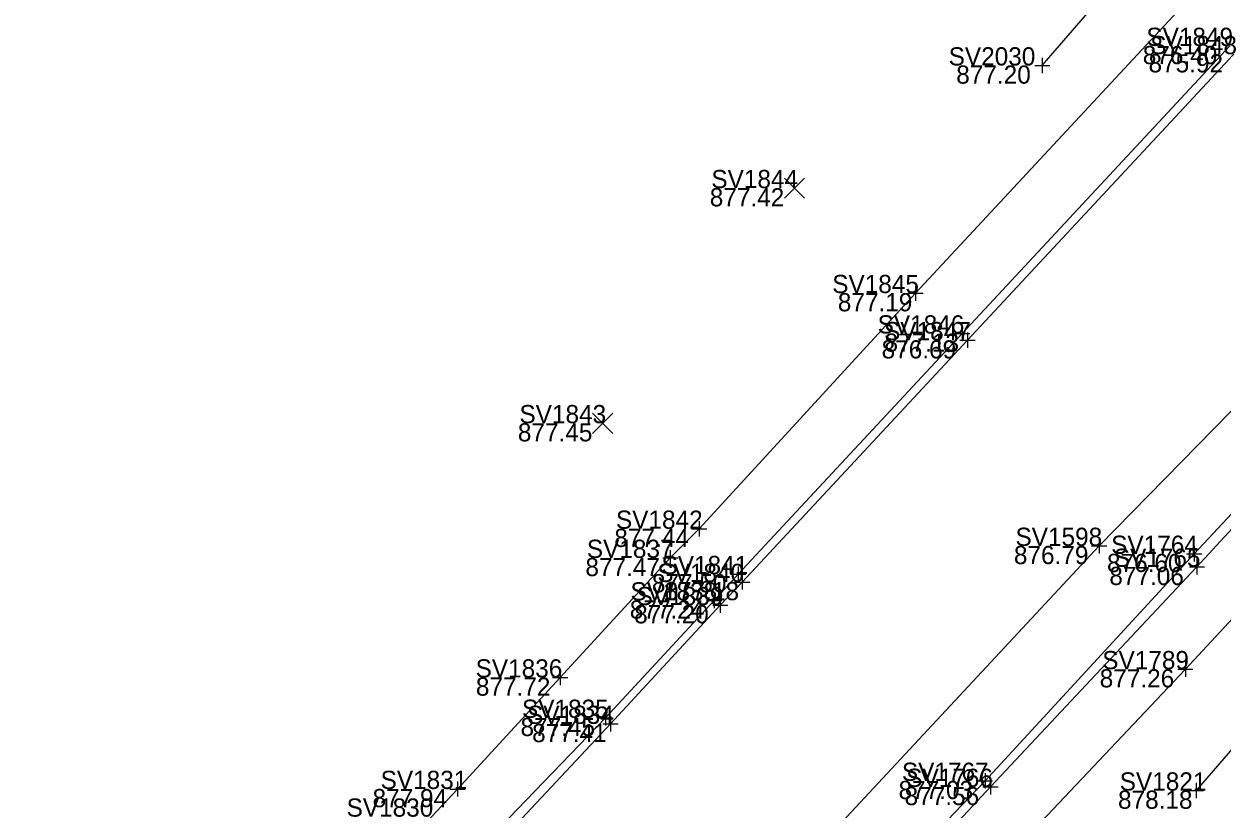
# Model space of a CAD drawing. Extents: x 1480001 to 1480402, y 379235 to 379603.
# Drawn here: x 1480035.5 to 1480114.4, y 379318.4 to 379370.1 of the extents above; entities that cross this region are included whole.
import ezdxf

# ---------------------------------------------------------------- set-up
doc = ezdxf.new("R2010")
doc.units = 0
for name, color, linetype in [('PV_X_Curb', 7, 'Continuous'), ('PV_X_Walk', 7, 'Continuous'), ('SV_X_Break_Lines', 7, 'Continuous'), ('SV_X_Random_Point', 7, 'Continuous'), ('SV_X_Shot_Marker', 7, 'Continuous'), ('SV_X_Text_Elevation', 7, 'Continuous'), ('SV_X_Text_Name', 7, 'Continuous'), ('UT_X_Water', 7, 'Continuous')]:
    doc.layers.add(name, color=color, linetype=linetype)

msp = doc.modelspace()

# ---------------------------------------------------------------- linework, layer by layer
at = {"layer": 'PV_X_Curb'}
for points in [[(1480155.238, 379379.795), (1480153.548, 379379.014), (1480146.824, 379371.927), (1480145.567, 379370.605), (1480143.964, 379368.78), (1480128.12, 379351.892), (1480112.56, 379335.214), (1480098.785, 379320.255), (1480094.793, 379316.092), (1480093.124, 379314.172), (1480085.166, 379305.624), (1480081.585, 379301.702), (1480079.854, 379299.882), (1480067.172, 379286.11), (1480056.531, 379274.485), (1480055.169, 379272.969)], [(1480155.431, 379379.884), (1480153.98, 379378.667), (1480147.216, 379371.505), (1480146.047, 379370.27), (1480144.119, 379368.047), (1480128.647, 379351.629), (1480112.741, 379334.357), (1480099.146, 379319.858), (1480095.569, 379316.008), (1480093.53, 379313.846), (1480085.356, 379305.01), (1480081.967, 379301.397), (1480080.218, 379299.413), (1480067.589, 379285.613), (1480056.688, 379273.774), (1480055.547, 379272.623)], [(1480038.409, 379286.458), (1480053.445, 379302.656), (1480065.083, 379315.224), (1480066.832, 379317.181), (1480073.782, 379324.407), (1480080.94, 379332.144), (1480082.529, 379333.877), (1480097.272, 379349.731), (1480114.906, 379368.678)], [(1480038.979, 379286.174), (1480053.858, 379302.215), (1480065.464, 379314.71), (1480067.296, 379316.727), (1480074.111, 379324.008), (1480081.345, 379331.835), (1480082.794, 379333.357), (1480097.622, 379349.287), (1480115.163, 379368.135)]]:
    msp.add_lwpolyline(points, dxfattribs=at)
at = {"layer": 'PV_X_Walk'}
for points in [[(1480035.484, 379289.224), (1480050.568, 379305.437), (1480062.335, 379317.896), (1480064.038, 379319.719), (1480070.805, 379327.066), (1480078.054, 379334.946), (1480079.953, 379336.866), (1480094.208, 379352.393), (1480112.048, 379371.575), (1480117.348, 379377.211), (1480119.911, 379379.906), (1480121.511, 379381.77), (1480134.604, 379395.58), (1480136.695, 379398.148), (1480138.778, 379401.149), (1480140.004, 379404.725), (1480140.577, 379408.06), (1480140.982, 379411.311), (1480140.871, 379414.584), (1480140.225, 379417.636), (1480139.184, 379419.586), (1480133.124, 379425.845), (1480132.903, 379425.968), (1480114.834, 379442.96)], [(1480059.793, 379271.54), (1480075.261, 379288.048), (1480088.444, 379302.419), (1480096.088, 379310.695), (1480098.33, 379313.163), (1480111.975, 379327.613), (1480128.977, 379345.933), (1480145.46, 379363.52), (1480153.413, 379372.021), (1480155.772, 379374.786), (1480158.213, 379377.107), (1480160.137, 379378.801), (1480161.631, 379379.994)]]:
    msp.add_lwpolyline(points, dxfattribs=at)
at = {"layer": 'SV_X_Break_Lines'}
for points in [[(1480102.555, 379367.391), (1480110.126, 379376.156), (1480117.553, 379385.207), (1480124.442, 379393.548)], [(1480184.481, 379363.392), (1480180.224, 379367.084), (1480176.21, 379371.695), (1480171.222, 379375.535), (1480168.077, 379375.239), (1480160.326, 379371.415), (1480150.91, 379361.854), (1480140.301, 379350.86), (1480130.798, 379340.93), (1480121.664, 379330.001), (1480112.679, 379319.616)]]:
    msp.add_lwpolyline(points, dxfattribs=at)
at = {"layer": 'SV_X_Random_Point'}
for p, q in [((1480085.569, 379358.641), (1480086.903, 379359.976)), ((1480085.569, 379359.976), (1480086.903, 379358.641)), ((1480072.94, 379343.152), (1480074.274, 379344.487)), ((1480072.94, 379344.487), (1480074.274, 379343.152))]:
    msp.add_line(p, q, dxfattribs=at)
at = {"layer": 'SV_X_Shot_Marker'}
for p, q in [((1480102.555, 379367.891), (1480102.555, 379366.891)), ((1480102.055, 379367.391), (1480103.055, 379367.391)), ((1480102.555, 379367.391), (1480102.555, 379367.391)), ((1480094.208, 379352.893), (1480094.208, 379351.893)), ((1480093.708, 379352.393), (1480094.708, 379352.393)), ((1480094.208, 379352.393), (1480094.208, 379352.393)), ((1480096.772, 379349.731), (1480097.772, 379349.731)), ((1480097.272, 379350.231), (1480097.272, 379349.231)), ((1480097.272, 379349.731), (1480097.272, 379349.731)), ((1480097.622, 379349.787), (1480097.622, 379348.787)), ((1480097.122, 379349.287), (1480098.122, 379349.287)), ((1480097.622, 379349.287), (1480097.622, 379349.287)), ((1480079.953, 379337.366), (1480079.953, 379336.366)), ((1480079.453, 379336.866), (1480080.453, 379336.866)), ((1480079.953, 379336.866), (1480079.953, 379336.866)), ((1480105.797, 379335.736), (1480106.797, 379335.736)), ((1480106.297, 379336.236), (1480106.297, 379335.236)), ((1480106.297, 379335.736), (1480106.297, 379335.736)), ((1480112.56, 379335.714), (1480112.56, 379334.714)), ((1480077.554, 379334.946), (1480078.554, 379334.946)), ((1480078.054, 379335.446), (1480078.054, 379334.446)), ((1480078.054, 379334.946), (1480078.054, 379334.946)), ((1480112.06, 379335.214), (1480113.06, 379335.214)), ((1480112.56, 379335.214), (1480112.56, 379335.214)), ((1480112.741, 379334.857), (1480112.741, 379333.857)), ((1480082.529, 379334.377), (1480082.529, 379333.377)), ((1480112.241, 379334.357), (1480113.241, 379334.357)), ((1480112.741, 379334.357), (1480112.741, 379334.357)), ((1480082.029, 379333.877), (1480083.029, 379333.877)), ((1480082.294, 379333.357), (1480083.294, 379333.357)), ((1480082.529, 379333.877), (1480082.529, 379333.877)), ((1480082.794, 379333.857), (1480082.794, 379332.857)), ((1480082.794, 379333.357), (1480082.794, 379333.357)), ((1480080.94, 379332.644), (1480080.94, 379331.644)), ((1480081.345, 379332.335), (1480081.345, 379331.335)), ((1480080.44, 379332.144), (1480081.44, 379332.144)), ((1480080.845, 379331.835), (1480081.845, 379331.835)), ((1480080.94, 379332.144), (1480080.94, 379332.144)), ((1480081.345, 379331.835), (1480081.345, 379331.835)), ((1480070.805, 379327.566), (1480070.805, 379326.566)), ((1480111.475, 379327.613), (1480112.475, 379327.613)), ((1480111.975, 379328.113), (1480111.975, 379327.113)), ((1480111.975, 379327.613), (1480111.975, 379327.613)), ((1480070.305, 379327.066), (1480071.305, 379327.066)), ((1480070.805, 379327.066), (1480070.805, 379327.066)), ((1480073.782, 379324.907), (1480073.782, 379323.907)), ((1480074.111, 379324.508), (1480074.111, 379323.508)), ((1480073.282, 379324.407), (1480074.282, 379324.407)), ((1480073.611, 379324.008), (1480074.611, 379324.008)), ((1480073.782, 379324.407), (1480073.782, 379324.407)), ((1480074.111, 379324.008), (1480074.111, 379324.008)), ((1480098.785, 379320.755), (1480098.785, 379319.755)), ((1480063.538, 379319.719), (1480064.538, 379319.719)), ((1480064.038, 379320.219), (1480064.038, 379319.219)), ((1480064.038, 379319.719), (1480064.038, 379319.719)), ((1480098.285, 379320.255), (1480099.285, 379320.255)), ((1480098.646, 379319.858), (1480099.646, 379319.858)), ((1480098.785, 379320.255), (1480098.785, 379320.255)), ((1480099.146, 379320.358), (1480099.146, 379319.358)), ((1480099.146, 379319.858), (1480099.146, 379319.858)), ((1480112.679, 379320.116), (1480112.679, 379319.116)), ((1480112.179, 379319.616), (1480113.179, 379319.616)), ((1480112.679, 379319.616), (1480112.679, 379319.616))]:
    msp.add_line(p, q, dxfattribs=at)
at = {"layer": 'UT_X_Water'}
msp.add_lwpolyline([(1480169.204, 379397.823), (1480165.761, 379394.087), (1480162.59, 379391.88), (1480159.156, 379388.706), (1480148.911, 379378.819), (1480120.344, 379350.087), (1480106.297, 379335.736), (1480080.736, 379308.289), (1480073.091, 379299.637), (1480056.748, 379281.628), (1480051.266, 379275.974)], dxfattribs=at)

# ---------------------------------------------------------------- texts
at = {"layer": 'SV_X_Text_Elevation'}
for s, p in [('876.40', (1480109.171, 379367.478)), ('875.92', (1480109.551, 379366.935)), ('877.20', (1480096.886, 379366.191)), ('877.42', (1480080.652, 379358.109)), ('877.19', (1480089.088, 379351.193)), ('877.13', (1480092.161, 379348.531)), ('876.69', (1480091.972, 379348.087)), ('877.45', (1480068.014, 379342.62)), ('877.44', (1480074.369, 379335.666)), ('876.79', (1480100.685, 379334.536)), ('877.47', (1480072.461, 379333.746)), ('876.60', (1480106.815, 379334.014)), ('877.50', (1480076.841, 379332.677)), ('877.06', (1480106.968, 379333.157)), ('877.18', (1480077.674, 379332.157)), ('877.24', (1480075.384, 379330.944)), ('877.20', (1480075.676, 379330.635)), ('877.26', (1480106.334, 379326.413)), ('877.72', (1480065.249, 379325.866)), ('877.45', (1480068.189, 379323.207)), ('877.41', (1480068.952, 379322.808)), ('877.94', (1480058.445, 379318.519)), ('877.03', (1480093.088, 379319.055)), ('877.56', (1480093.487, 379318.658)), ('878.18', (1480107.54, 379318.416))]:
    msp.add_text(s, height=1.2, dxfattribs=at).set_placement(p)
at = {"layer": 'SV_X_Text_Name'}
for s, p in [('SV1849', (1480109.408, 379368.678)), ('SV2030', (1480096.385, 379367.391)), ('SV1848', (1480109.665, 379368.135)), ('SV1844', (1480080.757, 379359.309)), ('SV1845', (1480088.719, 379352.393)), ('SV1846', (1480091.708, 379349.731)), ('SV1847', (1480092.133, 379349.287)), ('SV1843', (1480068.118, 379343.82)), ('SV1842', (1480074.474, 379336.866)), ('SV1598', (1480100.789, 379335.736)), ('SV1764', (1480107.09, 379335.214)), ('SV1837', (1480072.556, 379334.946)), ('SV1765', (1480107.262, 379334.357)), ('SV1841', (1480077.474, 379333.877)), ('SV1840', (1480077.201, 379333.357)), ('SV1838', (1480075.432, 379332.144)), ('SV1839', (1480075.837, 379331.835)), ('SV1789', (1480106.505, 379327.613)), ('SV1836', (1480065.231, 379327.066)), ('SV1835', (1480068.284, 379324.407)), ('SV1834', (1480068.622, 379324.008)), ('SV1767', (1480093.306, 379320.255)), ('SV1831', (1480058.974, 379319.719)), ('SV1766', (1480093.591, 379319.858)), ('SV1821', (1480107.652, 379319.616)), ('SV1830', (1480056.733, 379317.896))]:
    msp.add_text(s, height=1.2, dxfattribs=at).set_placement(p)

doc.saveas('drawing.dxf')
